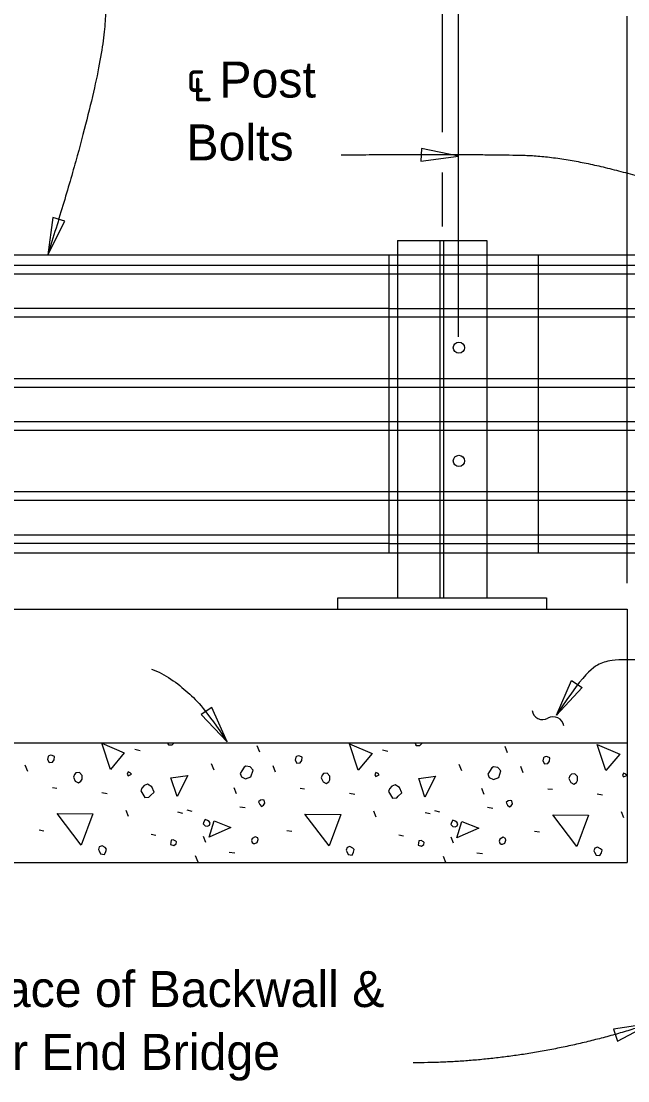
# Model space of a CAD drawing. Extents: x 21526.6 to 21598.7, y 56118.1 to 56155.9.
# Drawn here: x 21550.79 to 21554.18, y 56132.57 to 56138.5 of the extents above; entities that cross this region are included whole.
import ezdxf

# ---------------------------------------------------------------- set-up
doc = ezdxf.new("R2010")
doc.units = 0
for name, color, linetype in [('AdhocPoint_dp', 7, 'Continuous'), ('Patterning', 7, 'Continuous'), ('PlotBorder_dp', 7, 'Continuous'), ('SheetBorder_dp', 7, 'Continuous'), ('TextMisc', 7, 'Continuous')]:
    doc.layers.add(name, color=color, linetype=linetype)

msp = doc.modelspace()

# ---------------------------------------------------------------- linework, layer by layer
at = {"layer": 'AdhocPoint_dp'}
for p, q in [((21546.3955, 56135.21), (21554.1792, 56135.21)), ((21554.1792, 56135.21), (21554.1792, 56133.7933)), ((21554.1792, 56134.46), (21546.3955, 56134.46)), ((21546.3955, 56133.7933), (21554.1792, 56133.7933))]:
    msp.add_line(p, q, dxfattribs=at)
at = {"layer": 'Patterning'}
for p, q in [((21553.2368, 56136.733), (21553.2368, 56140.7989)), ((21553.1455, 56139.7166), (21553.1455, 56137.8785)), ((21553.1455, 56137.6522), (21553.1455, 56137.3509)), ((21552.1266, 56134.4099), (21552.1125, 56134.4452)), ((21553.5113, 56134.4063), (21553.4972, 56134.4417)), ((21551.4284, 56134.4258), (21551.4567, 56134.4187)), ((21552.8131, 56134.4222), (21552.8413, 56134.4152)), ((21550.8297, 56134.3009), (21550.8156, 56134.3362)), ((21551.8703, 56134.3091), (21551.8562, 56134.3444)), ((21552.2144, 56134.2973), (21552.2003, 56134.3327)), ((21553.255, 56134.3056), (21553.2409, 56134.3409)), ((21553.5991, 56134.2938), (21553.5849, 56134.3292)), ((21550.9676, 56134.2125), (21550.9924, 56134.209)), ((21551.9958, 56134.1765), (21551.9835, 56134.2101)), ((21552.3523, 56134.209), (21552.377, 56134.2054)), ((21553.3805, 56134.173), (21553.3681, 56134.2066)), ((21553.737, 56134.2054), (21553.7617, 56134.2019)), ((21551.2434, 56134.1842), (21551.2734, 56134.1789)), ((21552.6281, 56134.1807), (21552.6581, 56134.1754)), ((21554.0127, 56134.1771), (21554.0428, 56134.1718)), ((21551.3919, 56134.0499), (21551.3795, 56134.0834)), ((21551.7183, 56134.0864), (21551.7466, 56134.0793)), ((21552.0147, 56134.1047), (21552.0447, 56134.0994)), ((21552.7766, 56134.0463), (21552.7642, 56134.0799)), ((21553.103, 56134.0828), (21553.1313, 56134.0757)), ((21553.3993, 56134.1011), (21553.4294, 56134.0958)), ((21551.6659, 56134.0764), (21551.6942, 56134.0693)), ((21553.0506, 56134.0728), (21553.0788, 56134.0658)), ((21554.1612, 56134.0428), (21554.1489, 56134.0764)), ((21550.8934, 56133.9756), (21550.9199, 56133.9703)), ((21552.278, 56133.9721), (21552.3046, 56133.9668)), ((21553.6627, 56133.9685), (21553.6892, 56133.9632)), ((21551.5192, 56133.9509), (21551.5457, 56133.9456)), ((21551.8244, 56133.9038), (21551.812, 56133.9373)), ((21552.9038, 56133.9473), (21552.9304, 56133.942)), ((21553.209, 56133.9002), (21553.1967, 56133.9338)), ((21551.9545, 56133.8501), (21551.9864, 56133.8466)), ((21553.3392, 56133.8466), (21553.371, 56133.843)), ((21551.7819, 56133.7942), (21551.7678, 56133.8295)), ((21553.1655, 56133.7933), (21553.1525, 56133.826))]:
    msp.add_line(p, q, dxfattribs=at)
for points in [[(21551.2911, 56134.3133), (21551.2434, 56134.46), (21551.3689, 56134.4052), (21551.2911, 56134.3133)], [(21551.6117, 56134.46), (21551.6158, 56134.4505), (21551.6122, 56134.454)], [(21551.6158, 56134.4505), (21551.637, 56134.4505), (21551.6464, 56134.46)], [(21552.6758, 56134.3097), (21552.6281, 56134.4564), (21552.7536, 56134.4016), (21552.6758, 56134.3097)], [(21552.9955, 56134.46), (21552.9951, 56134.4594), (21553.0004, 56134.447), (21552.9969, 56134.4505)], [(21553.0004, 56134.447), (21553.0217, 56134.447), (21553.0323, 56134.4576), (21553.0316, 56134.46)], [(21554.0605, 56134.3062), (21554.0127, 56134.4529), (21554.1383, 56134.3981), (21554.0605, 56134.3062)], [(21550.9393, 56134.3681), (21550.9482, 56134.3521), (21550.9676, 56134.3539), (21550.9765, 56134.3663), (21550.9782, 56134.3857), (21550.9658, 56134.391), (21550.957, 56134.3928), (21550.9464, 56134.3893), (21550.9429, 56134.3857), (21550.9393, 56134.3681)], [(21552.324, 56134.3645), (21552.3328, 56134.3486), (21552.3523, 56134.3504), (21552.3611, 56134.3627), (21552.3629, 56134.3822), (21552.3505, 56134.3875), (21552.3417, 56134.3893), (21552.3311, 56134.3857), (21552.3275, 56134.3822), (21552.324, 56134.3645)], [(21553.7087, 56134.361), (21553.7175, 56134.3451), (21553.737, 56134.3468), (21553.7458, 56134.3592), (21553.7476, 56134.3787), (21553.7352, 56134.384), (21553.7264, 56134.3857), (21553.7158, 56134.3822), (21553.7122, 56134.3787), (21553.7087, 56134.361)], [(21552.0241, 56134.272), (21552.0471, 56134.2596), (21552.0771, 56134.272), (21552.0895, 56134.3091), (21552.0718, 56134.3268), (21552.0489, 56134.3321), (21552.0383, 56134.325), (21552.0259, 56134.3056), (21552.017, 56134.2896), (21552.0241, 56134.272)], [(21553.4088, 56134.2684), (21553.4318, 56134.2561), (21553.4618, 56134.2684), (21553.4742, 56134.3056), (21553.4565, 56134.3232), (21553.4335, 56134.3285), (21553.4229, 56134.3215), (21553.4106, 56134.302), (21553.4017, 56134.2861), (21553.4088, 56134.2684)], [(21551.0843, 56134.2691), (21551.0949, 56134.2478), (21551.1126, 56134.2372), (21551.1267, 56134.2478), (21551.1338, 56134.2585), (21551.1338, 56134.2797), (21551.1179, 56134.2956), (21551.0984, 56134.2938), (21551.0896, 56134.285), (21551.0843, 56134.2691)], [(21551.3901, 56134.2779), (21551.4096, 56134.2867), (21551.4025, 56134.2938), (21551.3901, 56134.2991), (21551.3848, 56134.2867), (21551.3901, 56134.2779)], [(21551.6635, 56134.1624), (21551.6299, 56134.2667), (21551.7236, 56134.279), (21551.6635, 56134.1624)], [(21552.469, 56134.2655), (21552.4796, 56134.2443), (21552.4973, 56134.2337), (21552.5114, 56134.2443), (21552.5185, 56134.2549), (21552.5185, 56134.2761), (21552.5026, 56134.292), (21552.4831, 56134.2903), (21552.4743, 56134.2814), (21552.469, 56134.2655)], [(21552.7748, 56134.2744), (21552.7942, 56134.2832), (21552.7872, 56134.2903), (21552.7748, 56134.2956), (21552.7695, 56134.2832), (21552.7748, 56134.2744)], [(21553.0482, 56134.1588), (21553.0146, 56134.2631), (21553.1083, 56134.2755), (21553.0482, 56134.1588)], [(21553.8536, 56134.262), (21553.8643, 56134.2408), (21553.8819, 56134.2302), (21553.8961, 56134.2408), (21553.9031, 56134.2514), (21553.9031, 56134.2726), (21553.8872, 56134.2885), (21553.8678, 56134.2867), (21553.8589, 56134.2779), (21553.8536, 56134.262)], [(21554.1595, 56134.2708), (21554.1789, 56134.2797), (21554.1718, 56134.2867), (21554.1595, 56134.292), (21554.1542, 56134.2797), (21554.1595, 56134.2708)], [(21551.4608, 56134.193), (21551.4838, 56134.1559), (21551.5068, 56134.1577), (21551.5156, 56134.1665), (21551.5351, 56134.186), (21551.5227, 56134.216), (21551.4979, 56134.2302), (21551.4803, 56134.2231), (21551.4661, 56134.209), (21551.4608, 56134.193)], [(21552.8455, 56134.1895), (21552.8685, 56134.1524), (21552.8915, 56134.1542), (21552.9003, 56134.163), (21552.9197, 56134.1824), (21552.9074, 56134.2125), (21552.8826, 56134.2266), (21552.8649, 56134.2196), (21552.8508, 56134.2054), (21552.8455, 56134.1895)], [(21552.126, 56134.117), (21552.1366, 56134.1064), (21552.1472, 56134.1135), (21552.1543, 56134.1241), (21552.1508, 56134.1418), (21552.1419, 56134.1435), (21552.1296, 56134.1418), (21552.1189, 56134.1312), (21552.126, 56134.117)], [(21553.5107, 56134.1135), (21553.5213, 56134.1029), (21553.5319, 56134.11), (21553.539, 56134.1206), (21553.5354, 56134.1382), (21553.5266, 56134.14), (21553.5142, 56134.1382), (21553.5036, 56134.1276), (21553.5107, 56134.1135)], [(21551.1285, 56133.889), (21550.9941, 56134.0658), (21551.1939, 56134.064), (21551.1285, 56133.889)], [(21551.8208, 56133.998), (21551.8332, 56133.9962), (21551.8456, 56134.0015), (21551.8491, 56134.0121), (21551.8438, 56134.0209), (21551.8332, 56134.028), (21551.8208, 56134.0333), (21551.8138, 56134.0192), (21551.8102, 56134.0086), (21551.8208, 56133.998)], [(21551.8432, 56133.9332), (21551.8715, 56134.0251), (21551.9652, 56133.988), (21551.8432, 56133.9332)], [(21552.5132, 56133.8855), (21552.3788, 56134.0622), (21552.5786, 56134.0605), (21552.5132, 56133.8855)], [(21553.2055, 56133.9944), (21553.2179, 56133.9927), (21553.2302, 56133.998), (21553.2338, 56134.0086), (21553.2285, 56134.0174), (21553.2179, 56134.0245), (21553.2055, 56134.0298), (21553.1984, 56134.0156), (21553.1949, 56134.005), (21553.2055, 56133.9944)], [(21553.2279, 56133.9296), (21553.2561, 56134.0216), (21553.3498, 56133.9844), (21553.2279, 56133.9296)], [(21553.8978, 56133.8819), (21553.7635, 56134.0587), (21553.9632, 56134.0569), (21553.8978, 56133.8819)], [(21551.627, 56133.8925), (21551.6464, 56133.8872), (21551.6588, 56133.8961), (21551.6606, 56133.9084), (21551.657, 56133.912), (21551.6429, 56133.919), (21551.6305, 56133.9173), (21551.6288, 56133.9049), (21551.627, 56133.8925)], [(21552.0907, 56133.8978), (21552.0977, 56133.8978), (21552.1119, 56133.9049), (21552.1172, 56133.9208), (21552.1154, 56133.9296), (21552.1013, 56133.9367), (21552.0836, 56133.9261), (21552.0801, 56133.9155), (21552.0836, 56133.9049), (21552.0907, 56133.8978)], [(21553.0117, 56133.889), (21553.0311, 56133.8837), (21553.0435, 56133.8925), (21553.0453, 56133.9049), (21553.0417, 56133.9084), (21553.0276, 56133.9155), (21553.0152, 56133.9137), (21553.0134, 56133.9014), (21553.0117, 56133.889)], [(21553.4753, 56133.8943), (21553.4824, 56133.8943), (21553.4966, 56133.9014), (21553.5019, 56133.9173), (21553.5001, 56133.9261), (21553.4859, 56133.9332), (21553.4683, 56133.9226), (21553.4647, 56133.912), (21553.4683, 56133.9014), (21553.4753, 56133.8943)], [(21551.2275, 56133.8572), (21551.2363, 56133.8413), (21551.2575, 56133.8377), (21551.2664, 56133.8536), (21551.2699, 56133.8678), (21551.2611, 56133.8766), (21551.2452, 56133.8855), (21551.2292, 56133.8801), (21551.2239, 56133.8642), (21551.2275, 56133.8572)], [(21552.6122, 56133.8536), (21552.621, 56133.8377), (21552.6422, 56133.8342), (21552.651, 56133.8501), (21552.6546, 56133.8642), (21552.6457, 56133.8731), (21552.6298, 56133.8819), (21552.6139, 56133.8766), (21552.6086, 56133.8607), (21552.6122, 56133.8536)], [(21553.9968, 56133.8501), (21554.0057, 56133.8342), (21554.0269, 56133.8307), (21554.0357, 56133.8466), (21554.0393, 56133.8607), (21554.0304, 56133.8695), (21554.0145, 56133.8784), (21553.9986, 56133.8731), (21553.9933, 56133.8572), (21553.9968, 56133.8501)]]:
    msp.add_lwpolyline(points, dxfattribs=at)
at = {"layer": 'PlotBorder_dp'}
msp.add_line((21554.1792, 56135.3555), (21554.1792, 56138.5276), dxfattribs=at)
for points in [[(21553.2368, 56137.7435), (21553.03, 56137.7865), (21553.0274, 56137.7159)], [(21550.9412, 56137.1914), (21551.037, 56137.3796), (21550.9697, 56137.4007)], [(21553.7845, 56134.6171), (21553.8687, 56134.8109), (21553.9278, 56134.7723)], [(21551.9438, 56134.4667), (21551.8573, 56134.6594), (21551.7987, 56134.6201)], [(21554.3117, 56132.8915), (21554.1029, 56132.8596), (21554.1251, 56132.7926)]]:
    msp.add_lwpolyline(points, close=True, dxfattribs=at)
for centre, start, end in [((21553.707, 56134.6515), 187.95358, 299.6808), ((21553.766, 56134.5479), 7.95358, 119.6808)]:
    msp.add_arc(centre, 0.0596, start, end, dxfattribs=at)
for points, degree in [([(21550.9412, 56138.9423), (21551.0716, 56138.9423), (21551.2923, 56138.8019), (21551.2221, 56138.0895), (21550.9412, 56137.1914)], 2), ([(21552.581, 56137.751), (21553.1726, 56137.7569), (21553.9973, 56137.7421), (21554.7081, 56137.4746)], 2), ([(21554.6745, 56134.9046), (21554.1531, 56134.9384), (21554.0496, 56134.9162), (21553.9557, 56134.8796), (21553.7845, 56134.6171)], 3), ([(21551.5214, 56134.8744), (21551.5962, 56134.8489), (21551.7392, 56134.7394), (21551.8231, 56134.647), (21551.9438, 56134.4666)], 3), ([(21554.3117, 56132.8915), (21553.648, 56132.6719), (21552.9843, 56132.6719)], 2)]:
    msp.add_open_spline(points, degree=degree, dxfattribs=at)
at = {"layer": 'SheetBorder_dp'}
for p, q in [((21553.1351, 56135.2724), (21553.1351, 56137.2724)), ((21553.1559, 56135.2724), (21553.1559, 56137.2724)), ((21552.8484, 56137.1891), (21552.8484, 56135.5224)), ((21564.1633, 56137.1891), (21552.8484, 56137.1891)), ((21552.8955, 56137.1891), (21552.8955, 56135.5224)), ((21553.3955, 56137.1891), (21553.3955, 56135.5224)), ((21553.6817, 56137.1891), (21553.6817, 56135.5224)), ((21552.8484, 56137.1336), (21564.1633, 56137.1336)), ((21552.8484, 56137.0853), (21564.1633, 56137.0853)), ((21552.8484, 56136.8925), (21564.1633, 56136.8925)), ((21552.8484, 56136.8443), (21564.1633, 56136.8443)), ((21552.8484, 56136.5003), (21564.1633, 56136.5003)), ((21552.8484, 56136.4521), (21564.1633, 56136.4521)), ((21552.8484, 56136.2593), (21564.1633, 56136.2593)), ((21552.8484, 56136.2112), (21564.1633, 56136.2112)), ((21552.8484, 56135.8672), (21564.1633, 56135.8672)), ((21552.8484, 56135.819), (21564.1633, 56135.819)), ((21552.8484, 56135.6262), (21564.1633, 56135.6262)), ((21552.8484, 56135.5779), (21564.1633, 56135.5779)), ((21564.1633, 56135.5224), (21552.8484, 56135.5224))]:
    msp.add_line(p, q, dxfattribs=at)
at = {"layer": 'TextMisc'}
for p, q in [((21552.8955, 56137.2724), (21553.3955, 56137.2724)), ((21552.8955, 56137.2724), (21552.8955, 56137.1892)), ((21553.3955, 56137.2724), (21553.3955, 56137.1891)), ((21552.8484, 56137.1892), (21546.3955, 56137.1892)), ((21546.3955, 56137.1336), (21552.8484, 56137.1336)), ((21546.3955, 56137.0854), (21552.8484, 56137.0854)), ((21546.3955, 56136.8926), (21552.8484, 56136.8926)), ((21546.3955, 56136.8444), (21552.8484, 56136.8444)), ((21546.3955, 56136.5004), (21552.8484, 56136.5004)), ((21546.3955, 56136.4522), (21552.8484, 56136.4522)), ((21546.3955, 56136.2594), (21552.8484, 56136.2594)), ((21546.3955, 56136.2112), (21552.8484, 56136.2112)), ((21546.3955, 56135.8673), (21552.8484, 56135.8673)), ((21546.3955, 56135.8191), (21552.8484, 56135.8191)), ((21546.3955, 56135.6262), (21552.8484, 56135.6262)), ((21546.3955, 56135.578), (21552.8484, 56135.578)), ((21552.8484, 56135.5225), (21546.3955, 56135.5225)), ((21552.8955, 56135.5224), (21552.8955, 56135.2724)), ((21553.3955, 56135.5224), (21553.3955, 56135.2724)), ((21552.5621, 56135.2724), (21553.7288, 56135.2724)), ((21552.5621, 56135.2099), (21552.5621, 56135.2724)), ((21552.8955, 56135.2724), (21553.3955, 56135.2724)), ((21553.7288, 56135.2724), (21553.7288, 56135.2099)), ((21552.5621, 56135.2099), (21553.7288, 56135.2099))]:
    msp.add_line(p, q, dxfattribs=at)
for centre in [(21553.2392, 56136.6723), (21553.2392, 56136.0392)]:
    msp.add_circle(centre, 0.0312, dxfattribs=at)

# ---------------------------------------------------------------- texts
at = {"layer": 'PlotBorder_dp'}
for s, p in [('℄ Post ', (21551.716, 56138.0718)), ('Bolts', (21551.716, 56137.7198)), ('Front Face of Backwall &', (21549.8265, 56132.9839)), ('Begin or End Bridge', (21549.8265, 56132.6319))]:
    msp.add_text(s, height=0.2016, dxfattribs=at).set_placement(p)

doc.saveas('drawing.dxf')
